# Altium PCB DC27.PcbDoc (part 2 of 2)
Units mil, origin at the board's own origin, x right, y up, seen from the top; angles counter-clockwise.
Board outline 2165.35 x 2165.35 mil, 4 copper layers (Top, Mid-Layer 1, Mid-Layer 2, Bottom), stack 65.59 mil thick; 50 components, 49 nets, 297 pads, 156 vias.
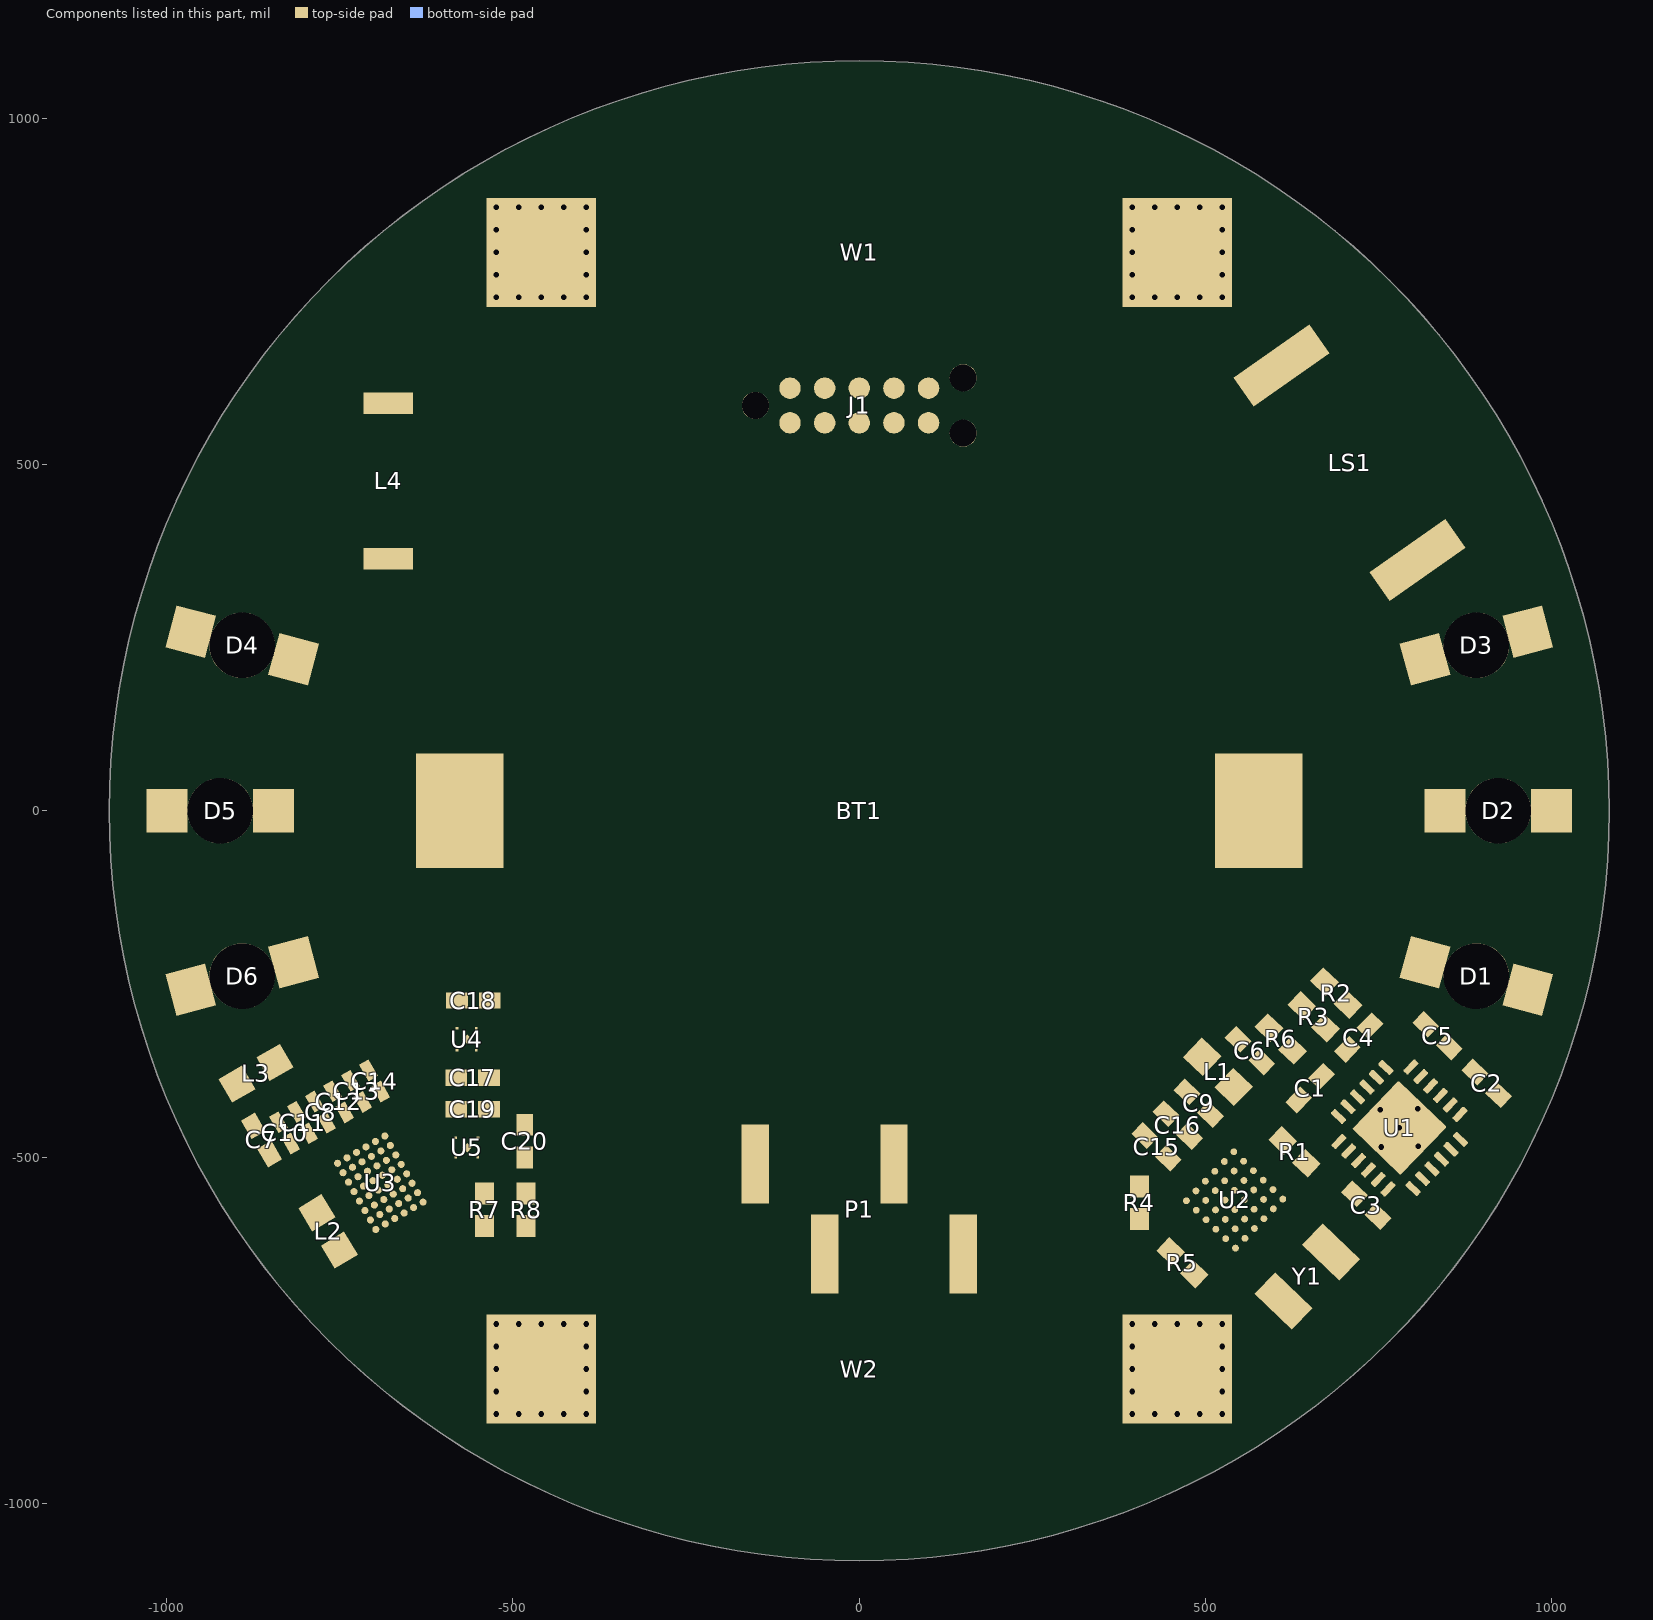
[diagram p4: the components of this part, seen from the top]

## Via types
v1: diameter 16, hole 8, Top to Bottom, 126 vias
v2: diameter 9.45, hole 4.92, Top to Mid-Layer 1, 15 vias
v3: diameter 9.06, hole 4.92, Top to Mid-Layer 1, 13 vias
v4: diameter 9.06, hole 4.92, Top to Bottom, 2 vias

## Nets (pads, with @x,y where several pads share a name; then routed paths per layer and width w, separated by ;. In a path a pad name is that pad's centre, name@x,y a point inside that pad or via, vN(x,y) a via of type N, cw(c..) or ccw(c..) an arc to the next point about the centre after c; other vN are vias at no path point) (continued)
copper on no net: | length 34526.6
  Top w0.89: -300.07,757.6 -249.32,757.6 ; -300.07,758.49 -244.87,758.49 ; -300.07,759.39 -241.3,759.39 ; -300.07,760.28 -236.85,760.28 ; -300.07,761.17 -235.07,761.17 ; -300.07,762.06 -233.29,762.06 ; -300.07,762.95 -231.51,762.95 ; -300.07,763.84 -228.84,763.84 ; -300.07,764.73 -227.06,764.73 ; -300.07,765.62 -226.17,765.62 ; -300.07,766.51 -225.28,766.51 ; -300.07,767.4 -223.5,767.4 ; -300.07,768.29 -222.61,768.29 ; -300.07,769.18 -221.72,769.18 ; -300.07,770.07 -220.83,770.07 ; -300.07,770.96 -219.93,770.96 ; -300.07,771.85 -219.04,771.85 ; -300.07,772.74 -218.15,772.74 ; -300.07,773.63 -217.26,773.63 ; -300.07,774.52 -216.37,774.52 ; -300.07,775.41 -276.03,775.41 ; -300.07,776.3 -276.03,776.3 ; -300.07,777.19 -276.03,777.19 ; -300.07,778.08 -276.03,778.08 ; -300.07,778.97 -276.03,778.97 ; -300.07,779.86 -276.03,779.86 ; -300.07,780.75 -276.03,780.75 ; -300.07,781.64 -276.03,781.64 ; -300.07,782.53 -276.03,782.53 ; -300.07,783.43 -276.03,783.43 ; -300.07,784.32 -276.03,784.32 ; -300.07,785.21 -276.03,785.21 ; -300.07,786.1 -276.03,786.1 ; -300.07,786.99 -276.03,786.99 ; -300.07,787.88 -276.03,787.88 ; -300.07,788.77 -276.03,788.77 ; -300.07,789.66 -276.03,789.66 ; -300.07,790.55 -276.03,790.55 ; -300.07,791.44 -276.03,791.44 ; -300.07,792.33 -276.03,792.33 ; -300.07,793.22 -276.03,793.22 ; -300.07,794.11 -276.03,794.11 ; -300.07,795 -276.03,795 ; -300.07,795.89 -276.03,795.89 ; -300.07,796.78 -276.03,796.78 ; -300.07,797.67 -276.03,797.67 ; -300.07,798.56 -276.03,798.56 ; -300.07,799.45 -276.03,799.45 ; -300.07,800.34 -276.03,800.34 ; -300.07,801.23 -276.03,801.23 ; -300.07,802.12 -276.03,802.12 ; -300.07,803.01 -276.03,803.01 ; -300.07,803.9 -276.03,803.9 ; -300.07,804.79 -276.03,804.79 ; -300.07,805.68 -276.03,805.68 ; -300.07,806.57 -276.03,806.57 ; -300.07,807.47 -276.03,807.47 ; -300.07,808.36 -276.03,808.36 ; -300.07,809.25 -276.03,809.25 ; -300.07,810.14 -276.03,810.14 ; -300.07,811.03 -276.03,811.03 ; -300.07,811.92 -276.03,811.92 ; -300.07,812.81 -276.03,812.81 ; -300.07,813.7 -276.03,813.7 ; -300.07,814.59 -276.03,814.59 ; -300.07,815.48 -276.03,815.48 ; -300.07,816.37 -276.03,816.37 ; -300.07,817.26 -276.03,817.26 ; -300.07,818.15 -276.03,818.15 ; -300.07,819.04 -276.03,819.04 ; -300.07,819.93 -276.03,819.93 ; -300.07,820.82 -276.03,820.82 ; -300.07,821.71 -276.03,821.71 ; -300.07,822.6 -276.03,822.6 ; -300.07,823.49 -276.03,823.49 ; -300.07,824.38 -276.03,824.38 ; -300.07,825.27 -276.03,825.27 ; -300.07,826.16 -276.03,826.16 ; -300.07,827.05 -276.03,827.05 ; -300.07,827.94 -276.03,827.94 ; -300.07,828.83 -276.03,828.83 ; -300.07,829.72 -276.03,829.72 ; -300.07,830.61 -276.03,830.61 ; -300.07,831.51 -276.03,831.51 ; -300.07,832.4 -217.26,832.4 ; -300.07,833.29 -218.15,833.29 ; -300.07,834.18 -219.04,834.18 ; -300.07,835.07 -219.04,835.07 ; -300.07,835.96 -219.93,835.96 ; -300.07,836.85 -220.83,836.85 ; -300.07,837.74 -221.72,837.74 ; -300.07,838.63 -223.5,838.63 ; -300.07,839.52 -224.39,839.52 ; -300.07,840.41 -225.28,840.41 ; -300.07,841.3 -227.06,841.3 ; -300.07,842.19 -227.06,842.19 ; -300.07,843.08 -230.62,843.08 ; -300.07,843.97 -231.51,843.97 ; -300.07,844.86 -233.29,844.86 ; -300.07,845.75 -235.07,845.75 ; -300.07,846.64 -238.63,846.64 ; -300.07,847.53 -241.3,847.53 ; -300.07,848.42 -243.97,848.42 ; -300.07,849.31 -247.54,849.31 ; -299.18,756.71 -260,756.71 ; -299.18,850.2 -257.33,850.2 ; -253.77,775.41 -215.48,775.41 ; -253.77,831.51 -216.37,831.51 ; -251.1,830.61 -215.48,830.61 ; -247.54,776.3 -214.59,776.3 ; -246.65,777.19 -214.59,777.19 ; -246.65,829.72 -214.59,829.72 ; -244.87,778.08 -213.7,778.08 ; -244.87,828.83 -214.59,828.83 ; -243.08,778.97 -213.7,778.97 ; -243.08,779.86 -212.81,779.86 ; -243.08,827.05 -213.7,827.05 ; -243.08,827.94 -214.59,827.94 ; -241.3,826.16 -212.81,826.16 ; -240.41,780.75 -211.92,780.75 ; -239.52,781.64 -211.92,781.64 ; -239.52,782.53 -211.03,782.53 ; -239.52,824.38 -211.92,824.38 ; -239.52,825.27 -211.92,825.27 ; -238.63,783.43 -211.03,783.43 ; -238.63,823.49 -211.03,823.49 ; -237.74,784.32 -210.14,784.32 ; -237.74,822.6 -211.03,822.6 ; -236.85,785.21 -210.14,785.21 ; -236.85,821.71 -210.14,821.71 ; -235.96,786.1 -210.14,786.1 ; -235.96,820.82 -210.14,820.82 ; -235.07,786.99 -210.14,786.99 ; -235.07,787.88 -210.14,787.88 ; -235.07,788.77 -209.25,788.77 ; -235.07,818.15 -210.14,818.15 ; -235.07,819.04 -210.14,819.04 ; -235.07,819.93 -210.14,819.93 ; -234.18,789.66 -209.25,789.66 ; -234.18,790.55 -208.36,790.55 ; -234.18,791.44 -208.36,791.44 ; -234.18,815.48 -209.25,815.48 ; -234.18,816.37 -209.25,816.37 ; -234.18,817.26 -209.25,817.26 ; -233.29,792.33 -208.36,792.33 ; -233.29,793.22 -208.36,793.22 ; -233.29,813.7 -208.36,813.7 ; -233.29,814.59 -208.36,814.59 ; -232.4,794.11 -207.47,794.11 ; -232.4,795 -207.47,795 ; -232.4,795.89 -207.47,795.89 ; -232.4,796.78 -207.47,796.78 ; -232.4,809.25 -207.47,809.25 ; -232.4,810.14 -207.47,810.14 ; -232.4,811.03 -207.47,811.03 ; -232.4,811.92 -207.47,811.92 ; -232.4,812.81 -208.36,812.81 ; -231.51,797.67 -207.47,797.67 ; -231.51,798.56 -207.47,798.56 ; -231.51,799.45 -207.47,799.45 ; -231.51,800.34 -207.47,800.34 ; -231.51,801.23 -207.47,801.23 ; -231.51,802.12 -207.47,802.12 ; -231.51,803.01 -207.47,803.01 ; -231.51,803.9 -207.47,803.9 ; -231.51,804.79 -207.47,804.79 ; -231.51,805.68 -207.47,805.68 ; -231.51,806.57 -207.47,806.57 ; -231.51,807.47 -207.47,807.47 ; -231.51,808.36 -207.47,808.36 ; -189.66,756.71 -121.1,756.71 ; -189.66,757.6 -121.1,757.6 ; -189.66,758.49 -121.1,758.49 ; -189.66,759.39 -121.1,759.39 ; -189.66,760.28 -121.1,760.28 ; -189.66,761.17 -121.1,761.17 ; -189.66,762.06 -121.1,762.06 ; -189.66,762.95 -121.1,762.95 ; -189.66,763.84 -121.1,763.84 ; -189.66,764.73 -121.1,764.73 ; -189.66,765.62 -121.1,765.62 ; -189.66,766.51 -121.1,766.51 ; -189.66,767.4 -121.1,767.4 ; -189.66,768.29 -121.1,768.29 ; -189.66,769.18 -121.1,769.18 ; -189.66,770.07 -121.1,770.07 ; -189.66,770.96 -121.1,770.96 ; -189.66,771.85 -121.1,771.85 ; -189.66,772.74 -121.1,772.74 ; -189.66,773.63 -121.1,773.63 ; -189.66,774.52 -121.1,774.52 ; -189.66,775.41 -165.62,775.41 ; -189.66,776.3 -165.62,776.3 ; -189.66,777.19 -165.62,777.19 ; -189.66,778.08 -165.62,778.08 ; -189.66,778.97 -165.62,778.97 ; -189.66,779.86 -165.62,779.86 ; -189.66,780.75 -165.62,780.75 ; -189.66,781.64 -165.62,781.64 ; -189.66,782.53 -165.62,782.53 ; -189.66,783.43 -165.62,783.43 ; -189.66,784.32 -165.62,784.32 ; -189.66,785.21 -165.62,785.21 ; -189.66,786.1 -165.62,786.1 ; -189.66,786.99 -165.62,786.99 ; -189.66,787.88 -165.62,787.88 ; -189.66,788.77 -165.62,788.77 ; -189.66,789.66 -165.62,789.66 ; -189.66,790.55 -165.62,790.55 ; -189.66,791.44 -165.62,791.44 ; -189.66,792.33 -165.62,792.33 ; -189.66,793.22 -165.62,793.22 ; -189.66,794.11 -165.62,794.11 ; -189.66,795 -165.62,795 ; -189.66,795.89 -165.62,795.89 ; -189.66,796.78 -123.78,796.78 ; -189.66,797.67 -123.78,797.67 ; -189.66,798.56 -123.78,798.56 ; -189.66,799.45 -123.78,799.45 ; -189.66,800.34 -123.78,800.34 ; -189.66,801.23 -123.78,801.23 ; -189.66,802.12 -123.78,802.12 ; -189.66,803.01 -123.78,803.01 ; -189.66,803.9 -123.78,803.9 ; -189.66,804.79 -123.78,804.79 ; -189.66,805.68 -123.78,805.68 ; -189.66,806.57 -123.78,806.57 ; -189.66,807.47 -123.78,807.47 ; -189.66,808.36 -123.78,808.36 ; -189.66,809.25 -123.78,809.25 ; -189.66,810.14 -123.78,810.14 ; -189.66,811.03 -123.78,811.03 ; -189.66,811.92 -123.78,811.92 ; -189.66,812.81 -123.78,812.81 ; -189.66,813.7 -165.62,813.7 ; -189.66,814.59 -165.62,814.59 ; -189.66,815.48 -165.62,815.48 ; -189.66,816.37 -165.62,816.37 ; -189.66,817.26 -165.62,817.26 ; -189.66,818.15 -165.62,818.15 ; -189.66,819.04 -165.62,819.04 ; -189.66,819.93 -165.62,819.93 ; -189.66,820.82 -165.62,820.82 ; -189.66,821.71 -165.62,821.71 ; -189.66,822.6 -165.62,822.6 ; -189.66,823.49 -165.62,823.49 ; -189.66,824.38 -165.62,824.38 ; -189.66,825.27 -165.62,825.27 ; -189.66,826.16 -165.62,826.16 ; -189.66,827.05 -165.62,827.05 ; -189.66,827.94 -165.62,827.94 ; -189.66,828.83 -165.62,828.83 ; -189.66,829.72 -165.62,829.72 ; -189.66,830.61 -165.62,830.61 ; -189.66,831.51 -165.62,831.51 ; -189.66,832.4 -121.99,832.4 ; -189.66,833.29 -121.99,833.29 ; -189.66,834.18 -121.99,834.18 ; -189.66,835.07 -121.99,835.07 ; -189.66,835.96 -121.99,835.96 ; -189.66,836.85 -121.99,836.85 ; -189.66,837.74 -121.99,837.74 ; -189.66,838.63 -121.99,838.63 ; -189.66,839.52 -121.99,839.52 ; -189.66,840.41 -121.99,840.41 ; -189.66,841.3 -121.99,841.3 ; -189.66,842.19 -121.99,842.19 ; -189.66,843.08 -121.99,843.08 ; -189.66,843.97 -121.99,843.97 ; -189.66,844.86 -121.99,844.86 ; -189.66,845.75 -121.99,845.75 ; -189.66,846.64 -121.99,846.64 ; -189.66,847.53 -121.99,847.53 ; -189.66,848.42 -121.99,848.42 ; -189.66,849.31 -121.99,849.31 ; -189.66,850.2 -121.99,850.2 ; -103.3,757.6 -78.37,757.6 ; -103.3,758.49 -78.37,758.49 ; -103.3,759.39 -78.37,759.39 ; -103.3,760.28 -78.37,760.28 ; -103.3,761.17 -78.37,761.17 ; -103.3,762.06 -78.37,762.06 ; -103.3,762.95 -78.37,762.95 ; -103.3,763.84 -78.37,763.84 ; -103.3,764.73 -78.37,764.73 ; -103.3,765.62 -78.37,765.62 ; -103.3,766.51 -78.37,766.51 ; -103.3,767.4 -78.37,767.4 ; -103.3,768.29 -78.37,768.29 ; -103.3,769.18 -78.37,769.18 ; -103.3,770.07 -78.37,770.07 ; -103.3,770.96 -78.37,770.96 ; -103.3,771.85 -78.37,771.85 ; -103.3,772.74 -78.37,772.74 ; -103.3,773.63 -78.37,773.63 ; -103.3,774.52 -78.37,774.52 ; -103.3,775.41 -78.37,775.41 ; -103.3,776.3 -78.37,776.3 ; -103.3,777.19 -78.37,777.19 ; -103.3,778.08 -78.37,778.08 ; -103.3,778.97 -78.37,778.97 ; -103.3,779.86 -78.37,779.86 ; -103.3,780.75 -78.37,780.75 ; -103.3,781.64 -78.37,781.64 ; -103.3,782.53 -78.37,782.53 ; -103.3,783.43 -78.37,783.43 ; -103.3,784.32 -78.37,784.32 ; -103.3,785.21 -78.37,785.21 ; -103.3,786.1 -78.37,786.1 ; -103.3,786.99 -78.37,786.99 ; -103.3,787.88 -78.37,787.88 ; -103.3,788.77 -78.37,788.77 ; -103.3,789.66 -78.37,789.66 ; -103.3,790.55 -78.37,790.55 ; -103.3,791.44 -78.37,791.44 ; -103.3,792.33 -78.37,792.33 ; -103.3,793.22 -78.37,793.22 ; -103.3,794.11 -78.37,794.11 ; -103.3,795 -39.19,795 ; -103.3,795.89 -38.3,795.89 ; -103.3,796.78 -38.3,796.78 ; -103.3,797.67 -38.3,797.67 ; -103.3,798.56 -38.3,798.56 ; -103.3,799.45 -38.3,799.45 ; -103.3,800.34 -38.3,800.34 ; -103.3,801.23 -38.3,801.23 ; -103.3,802.12 -38.3,802.12 ; -103.3,803.01 -38.3,803.01 ; -103.3,803.9 -38.3,803.9 ; -103.3,804.79 -38.3,804.79 ; -103.3,805.68 -38.3,805.68 ; -103.3,806.57 -38.3,806.57 ; -103.3,807.47 -38.3,807.47 ; -103.3,808.36 -38.3,808.36 ; -103.3,809.25 -38.3,809.25 ; -103.3,810.14 -38.3,810.14 ; -103.3,811.03 -38.3,811.03 ; -103.3,811.92 -38.3,811.92 ; -103.3,812.81 -78.37,812.81 ; -103.3,813.7 -78.37,813.7 ; -103.3,814.59 -78.37,814.59 ; -103.3,815.48 -78.37,815.48 ; -103.3,816.37 -78.37,816.37 ; -103.3,817.26 -78.37,817.26 ; -103.3,818.15 -78.37,818.15 ; -103.3,819.04 -78.37,819.04 ; -103.3,819.93 -78.37,819.93 ; -103.3,820.82 -78.37,820.82 ; -103.3,821.71 -78.37,821.71 ; -103.3,822.6 -78.37,822.6 ; -103.3,823.49 -78.37,823.49 ; -103.3,824.38 -78.37,824.38 ; -103.3,825.27 -78.37,825.27 ; -103.3,826.16 -78.37,826.16 ; -103.3,827.05 -78.37,827.05 ; -103.3,827.94 -78.37,827.94 ; -103.3,828.83 -78.37,828.83 ; -103.3,829.72 -78.37,829.72 ; -103.3,830.61 -78.37,830.61 ; -103.3,831.51 -78.37,831.51 ; -103.3,832.4 -39.19,832.4 ; -103.3,833.29 -38.3,833.29 ; -103.3,834.18 -38.3,834.18 ; -103.3,835.07 -38.3,835.07 ; -103.3,835.96 -38.3,835.96 ; -103.3,836.85 -38.3,836.85 ; -103.3,837.74 -38.3,837.74 ; -103.3,838.63 -38.3,838.63 ; -103.3,839.52 -38.3,839.52 ; -103.3,840.41 -38.3,840.41 ; -103.3,841.3 -38.3,841.3 ; -103.3,842.19 -38.3,842.19 ; -103.3,843.08 -38.3,843.08 ; -103.3,843.97 -38.3,843.97 ; -103.3,844.86 -38.3,844.86 ; -103.3,845.75 -38.3,845.75 ; -103.3,846.64 -38.3,846.64 ; -103.3,847.53 -38.3,847.53 ; -103.3,848.42 -38.3,848.42 ; -103.3,849.31 -38.3,849.31 ; -102.41,756.71 -79.26,756.71 ; -102.41,850.2 -39.19,850.2 ; -24.05,797.67 0.88,797.67 ; -24.05,798.56 0.88,798.56 ; -24.05,799.45 0.88,799.45 ; -24.05,800.34 0.88,800.34 ; -24.05,801.23 -0.01,801.23 ; -24.05,802.12 -0.01,802.12 ; -24.05,803.01 -0.01,803.01 ; -24.05,803.9 -0.01,803.9 ; -24.05,804.79 -0.01,804.79 ; -24.05,805.68 -0.01,805.68 ; -24.05,806.57 0.88,806.57 ; -24.05,807.47 0.88,807.47 ; -24.05,808.36 0.88,808.36 ; -23.16,793.22 2.66,793.22 ; -23.16,794.11 2.66,794.11 ; -23.16,795 1.77,795 ; -23.16,795.89 1.77,795.89 ; -23.16,796.78 1.77,796.78 ; -23.16,809.25 0.88,809.25 ; -23.16,810.14 1.77,810.14 ; -23.16,811.03 1.77,811.03 ; -23.16,811.92 1.77,811.92 ; -23.16,812.81 1.77,812.81 ; -22.27,790.55 4.44,790.55 ; -22.27,791.44 3.55,791.44 ; -22.27,792.33 3.55,792.33 ; -22.27,813.7 2.66,813.7 ; -22.27,814.59 3.55,814.59 ; -22.27,815.48 3.55,815.48 ; -21.38,788.77 4.44,788.77 ; -21.38,789.66 4.44,789.66 ; -21.38,816.37 4.44,816.37 ; -21.38,817.26 4.44,817.26 ; -20.49,785.21 8,785.21 ; -20.49,786.1 7.11,786.1 ; -20.49,786.99 6.22,786.99 ; -20.49,787.88 5.33,787.88 ; -20.49,818.15 5.33,818.15 ; -20.49,819.04 5.33,819.04 ; -20.49,819.93 6.22,819.93 ; -20.49,820.82 7.11,820.82 ; -19.6,783.43 9.78,783.43 ; -19.6,784.32 8.89,784.32 ; -19.6,821.71 8.89,821.71 ; -19.6,822.6 8.89,822.6 ; -18.71,781.64 12.45,781.64 ; -18.71,782.53 10.67,782.53 ; -18.71,823.49 9.78,823.49 ; -18.71,824.38 10.67,824.38 ; -17.82,780.75 12.45,780.75 ; -17.82,825.27 12.45,825.27 ; -16.93,778.97 16.9,778.97 ; -16.93,779.86 16.01,779.86 ; -16.93,826.16 14.23,826.16 ; -16.04,776.3 24.03,776.3 ; -16.04,777.19 21.35,777.19 ; -16.04,778.08 18.68,778.08 ; -16.04,827.05 16.01,827.05 ; -16.04,827.94 16.9,827.94 ; -16.04,828.83 18.68,828.83 ; -15.15,829.72 21.35,829.72 ; -14.26,775.41 66.76,775.41 ; -14.26,830.61 28.48,830.61 ; -13.37,773.63 66.76,773.63 ; -13.37,774.52 66.76,774.52 ; -13.37,831.51 65.87,831.51 ; -12.48,772.74 66.76,772.74 ; -12.48,832.4 65.87,832.4 ; -12.48,833.29 65.87,833.29 ; -11.59,771.85 66.76,771.85 ; -11.59,834.18 65.87,834.18 ; -10.7,770.96 66.76,770.96 ; -10.7,835.07 65.87,835.07 ; -9.81,770.07 66.76,770.07 ; -9.81,835.96 65.87,835.96 ; -8.92,769.18 66.76,769.18 ; -8.03,768.29 66.76,768.29 ; -8.03,836.85 65.87,836.85 ; -8.03,837.74 65.87,837.74 ; -6.25,767.4 66.76,767.4 ; -6.25,838.63 65.87,838.63 ; -5.36,766.51 66.76,766.51 ; -5.36,839.52 65.87,839.52 ; -4.47,765.62 66.76,765.62 ; -3.58,764.73 66.76,764.73 ; -3.58,840.41 65.87,840.41 ; -3.58,841.3 65.87,841.3 ; -2.68,763.84 65.87,763.84 ; -1.79,842.19 65.87,842.19 ; -0.01,762.95 62.31,762.95 ; -0.01,843.08 64.98,843.08 ; 1.77,762.06 60.53,762.06 ; 1.77,843.97 63.2,843.97 ; 3.55,761.17 58.75,761.17 ; 3.55,844.86 62.31,844.86 ; 4.44,760.28 57.86,760.28 ; 4.44,845.75 60.53,845.75 ; 8,846.64 57.86,846.64 ; 8.89,759.39 53.41,759.39 ; 9.78,847.53 55.19,847.53 ; 10.67,758.49 50.74,758.49 ; 12.45,848.42 52.52,848.42 ; 13.34,757.6 48.07,757.6 ; 15.12,849.31 49.85,849.31 ; 16.9,756.71 45.39,756.71 ; 18.68,850.2 46.29,850.2 ; 21.35,755.82 40.05,755.82 ; 39.16,830.61 65.87,830.61 ; 43.61,776.3 66.76,776.3 ; 46.29,777.19 66.76,777.19 ; 47.18,829.72 65.87,829.72 ; 48.96,778.08 66.76,778.08 ; 49.85,828.83 65.87,828.83 ; 50.74,778.97 66.76,778.97 ; 51.63,827.94 65.87,827.94 ; 53.41,779.86 66.76,779.86 ; 54.3,827.05 65.87,827.05 ; 56.08,826.16 65.87,826.16 ; 56.97,780.75 66.76,780.75 ; 57.86,781.64 66.76,781.64 ; 58.75,825.27 65.87,825.27 ; 59.64,782.53 66.76,782.53 ; 60.53,824.38 65.87,824.38 ; 61.42,783.43 66.76,783.43 ; 62.31,784.32 66.76,784.32 ; 62.31,823.49 65.87,823.49 ; 63.2,822.6 65.87,822.6 ; 64.98,821.71 65.87,821.71 ; 65.87,785.21 66.76,785.21 ; 81.01,795.89 124.64,795.89 ; 81.01,796.78 124.64,796.78 ; 81.01,797.67 121.08,797.67 ; 81.01,798.56 120.19,798.56 ; 81.01,799.45 119.3,799.45 ; 81.01,800.34 117.51,800.34 ; 81.01,801.23 114.84,801.23 ; 81.01,802.12 113.95,802.12 ; 81.01,803.01 112.17,803.01 ; 81.01,803.9 111.28,803.9 ; 81.01,804.79 109.5,804.79 ; 81.01,805.68 107.72,805.68 ; 81.01,806.57 92.58,806.57 ; 81.01,807.47 90.8,807.47 ; 81.01,808.36 90.8,808.36 ; 81.01,809.25 89.91,809.25 ; 81.01,810.14 89.02,810.14 ; 81.01,811.03 89.02,811.03 ; 81.9,791.44 128.2,791.44 ; 81.9,792.33 131.76,792.33 ; 81.9,793.22 129.09,793.22 ; 81.9,794.11 128.2,794.11 ; 81.9,795 126.42,795 ; 81.9,811.92 89.02,811.92 ; 81.9,812.81 89.02,812.81 ; 81.9,813.7 89.91,813.7 ; 81.9,814.59 89.91,814.59 ; 82.79,786.1 117.51,786.1 ; 82.79,786.99 119.3,786.99 ; 82.79,787.88 120.19,787.88 ; 82.79,788.77 123.75,788.77 ; 82.79,789.66 124.64,789.66 ; 82.79,790.55 126.42,790.55 ; 82.79,815.48 90.8,815.48 ; 82.79,816.37 90.8,816.37 ; 82.79,817.26 90.8,817.26 ; 82.79,818.15 95.26,818.15 ; 82.79,819.04 95.26,819.04 ; 82.79,819.93 95.26,819.93 ; 83.68,784.32 113.06,784.32 ; 83.68,785.21 115.73,785.21 ; 83.68,820.82 94.36,820.82 ; 83.68,821.71 94.36,821.71 ; 84.57,782.53 96.15,782.53 ; 84.57,783.43 97.04,783.43 ; 84.57,822.6 94.36,822.6 ; 84.57,823.49 94.36,823.49 ; 84.57,824.38 95.26,824.38 ; 85.46,780.75 95.26,780.75 ; 85.46,781.64 95.26,781.64 ; 85.46,825.27 95.26,825.27 ; 86.35,778.97 95.26,778.97 ; 86.35,779.86 95.26,779.86 ; 86.35,826.16 95.26,826.16 ; 86.35,827.05 96.15,827.05 ; 87.24,776.3 95.26,776.3 ; 87.24,777.19 95.26,777.19 ; 87.24,778.08 95.26,778.08 ; 87.24,827.94 98.82,827.94 ; 87.24,828.83 113.95,828.83 ; 87.24,829.72 114.84,829.72 ; 88.13,775.41 95.26,775.41 ; 88.13,830.61 115.73,830.61 ; 88.13,831.51 115.73,831.51 ; 89.02,773.63 96.15,773.63 ; 89.02,774.52 95.26,774.52 ; 89.02,832.4 115.73,832.4 ; 89.91,772.74 97.93,772.74 ; 89.91,833.29 115.73,833.29 ; 90.8,770.96 100.6,770.96 ; 90.8,771.85 101.49,771.85 ; 90.8,834.18 117.51,834.18 ; 90.8,835.07 117.51,835.07 ; 90.8,835.96 118.4,835.96 ; 91.69,769.18 99.71,769.18 ; 91.69,770.07 99.71,770.07 ; 91.69,836.85 119.3,836.85 ; 92.58,768.29 99.71,768.29 ; 92.58,837.74 120.19,837.74 ; 93.47,838.63 121.08,838.63 ; 94.36,767.4 99.71,767.4 ; 94.36,839.52 121.97,839.52 ; 95.26,764.73 100.6,764.73 ; 95.26,765.62 99.71,765.62 ; 95.26,766.51 99.71,766.51 ; 95.26,840.41 123.75,840.41 ; 95.26,841.3 124.64,841.3 ; 96.15,763.84 100.6,763.84 ; 96.15,806.57 105.94,806.57 ; 96.15,842.19 125.53,842.19 ; 97.93,762.95 103.27,762.95 ; 97.93,807.47 104.16,807.47 ; 97.93,843.08 128.2,843.08 ; 98.82,808.36 103.27,808.36 ; 98.82,843.97 130.87,843.97 ; 99.71,761.17 173.61,761.17 ; 99.71,762.06 174.5,762.06 ; 99.71,809.25 100.6,809.25 ; 99.71,827.94 113.95,827.94 ; 99.71,844.86 133.54,844.86 ; 99.71,845.75 173.61,845.75 ; 100.6,760.28 173.61,760.28 ; 102.38,759.39 170.94,759.39 ; 102.38,783.43 112.17,783.43 ; 102.38,827.05 113.95,827.05 ; 102.38,846.64 171.83,846.64 ; 103.27,758.49 170.05,758.49 ; 103.27,781.64 108.61,781.64 ; 103.27,782.53 110.39,782.53 ; 103.27,818.15 112.17,818.15 ; 103.27,819.04 112.17,819.04 ; 103.27,825.27 113.06,825.27 ; 103.27,826.16 113.06,826.16 ; 103.27,847.53 170.94,847.53 ; 103.27,848.42 170.05,848.42 ; 104.16,757.6 170.05,757.6 ; 104.16,780.75 107.72,780.75 ; 104.16,817.26 112.17,817.26 ; 104.16,819.93 112.17,819.93 ; 104.16,820.82 112.17,820.82 ; 104.16,821.71 112.17,821.71 ; 104.16,822.6 113.06,822.6 ; 104.16,823.49 113.06,823.49 ; 104.16,824.38 113.06,824.38 ; 105.05,756.71 168.27,756.71 ; 105.05,849.31 169.16,849.31 ; 105.94,816.37 113.06,816.37 ; 105.94,850.2 167.38,850.2 ; 106.83,755.82 167.38,755.82 ; 107.72,762.95 175.39,762.95 ; 107.72,814.59 113.06,814.59 ; 107.72,815.48 113.06,815.48 ; 107.72,851.09 165.59,851.09 ; 108.61,754.93 165.59,754.93 ; 108.61,763.84 166.48,763.84 ; 108.61,771.85 165.59,771.85 ; 108.61,772.74 165.59,772.74 ; 109.5,764.73 166.48,764.73 ; 109.5,765.62 165.59,765.62 ; 109.5,770.07 165.59,770.07 ; 109.5,770.96 165.59,770.96 ; 109.5,813.7 113.06,813.7 ; 109.5,851.98 164.7,851.98 ; 110.39,754.04 163.81,754.04 ; 110.39,766.51 165.59,766.51 ; 110.39,767.4 165.59,767.4 ; 110.39,768.29 165.59,768.29 ; 110.39,769.18 165.59,769.18 ; 110.39,773.63 164.7,773.63 ; 111.28,852.87 162.92,852.87 ; 112.17,753.15 162.03,753.15 ; 112.17,774.52 162.92,774.52 ; 112.17,812.81 113.95,812.81 ; 112.17,853.76 161.14,853.76 ; 113.06,752.26 161.14,752.26 ; 113.06,775.41 161.14,775.41 ; 113.95,854.65 160.25,854.65 ; 114.84,751.37 159.36,751.37 ; 115.73,776.3 159.36,776.3 ; 117.51,777.19 157.58,777.19 ; 117.51,855.55 156.69,855.55 ; 118.4,750.48 155.8,750.48 ; 118.4,818.15 124.64,818.15 ; 119.3,778.08 156.69,778.08 ; 119.3,817.26 123.75,817.26 ; 119.3,819.04 123.75,819.04 ; 120.19,749.59 153.13,749.59 ; 120.19,778.97 154.91,778.97 ; 120.19,812.81 123.75,812.81 ; 120.19,813.7 123.75,813.7 ; 120.19,814.59 122.86,814.59 ; 120.19,815.48 122.86,815.48 ; 120.19,816.37 122.86,816.37 ; 120.19,856.44 154.02,856.44 ; 121.08,811.03 124.64,811.03 ; 121.08,811.92 124.64,811.92 ; 121.97,779.86 153.13,779.86 ; 121.97,809.25 125.53,809.25 ; 121.97,810.14 124.64,810.14 ; 121.97,857.33 152.24,857.33 ; 123.75,748.7 150.46,748.7 ; 123.75,807.47 127.31,807.47 ; 123.75,808.36 126.42,808.36 ; 124.64,780.75 151.35,780.75 ; 124.64,805.68 129.09,805.68 ; 124.64,806.57 128.2,806.57 ; 124.64,826.16 135.32,826.16 ; 124.64,827.05 136.21,827.05 ; 124.64,827.94 136.21,827.94 ; 124.64,828.83 136.21,828.83 ; 124.64,829.72 135.32,829.72 ; 124.64,830.61 134.43,830.61 ; 124.64,858.22 148.68,858.22 ; 125.53,781.64 149.57,781.64 ; 125.53,825.27 134.43,825.27 ; 125.53,831.51 133.54,831.51 ; 126.42,747.81 146.9,747.81 ; 126.42,824.38 133.54,824.38 ; 126.42,832.4 132.65,832.4 ; 127.31,782.53 148.68,782.53 ; 127.31,804.79 132.65,804.79 ; 127.31,823.49 132.65,823.49 ; 128.2,783.43 147.79,783.43 ; 128.2,803.9 134.43,803.9 ; 128.2,833.29 131.76,833.29 ; 129.09,791.44 132.65,791.44 ; 129.09,803.01 147.79,803.01 ; 129.09,822.6 130.87,822.6 ; 129.98,784.32 146.01,784.32 ; 129.98,790.55 134.43,790.55 ; 130.87,802.12 146.01,802.12 ; 131.76,789.66 136.21,789.66 ; 132.65,785.21 143.34,785.21 ; 132.65,788.77 137.1,788.77 ; 132.65,801.23 144.23,801.23 ; 134.43,786.1 142.44,786.1 ; 136.21,786.99 140.66,786.99 ; 136.21,787.88 139.77,787.88 ; 141.55,803.9 148.68,803.9 ; 141.55,827.94 153.13,827.94 ; 141.55,828.83 153.13,828.83 ; 141.55,844.86 173.61,844.86 ; 142.44,826.16 153.13,826.16 ; 142.44,827.05 153.13,827.05 ; 142.44,829.72 153.13,829.72 ; 143.34,825.27 152.24,825.27 ; 143.34,830.61 153.13,830.61 ; 144.23,824.38 151.35,824.38 ; 144.23,831.51 152.24,831.51 ; 145.12,794.11 148.68,794.11 ; 145.12,795 147.79,795 ; 145.12,804.79 149.57,804.79 ; 145.12,823.49 150.46,823.49 ; 145.12,832.4 151.35,832.4 ; 145.12,843.97 175.39,843.97 ; 146.01,793.22 192.31,793.22 ; 146.01,833.29 149.57,833.29 ; 146.9,822.6 148.68,822.6 ; 147.79,805.68 151.35,805.68 ; 147.79,843.08 176.28,843.08 ; 148.68,792.33 191.42,792.33 ; 148.68,806.57 152.24,806.57 ; 148.68,807.47 153.13,807.47 ; 149.57,791.44 191.42,791.44 ; 149.57,808.36 153.13,808.36 ; 150.46,794.11 192.31,794.11 ; 150.46,842.19 178.06,842.19 ; 151.35,790.55 191.42,790.55 ; 151.35,809.25 154.91,809.25 ; 152.24,795 192.31,795 ; 152.24,810.14 154.91,810.14 ; 152.24,811.03 155.8,811.03 ; 152.24,841.3 178.06,841.3 ; 153.13,788.77 190.52,788.77 ; 153.13,789.66 191.42,789.66 ; 153.13,795.89 192.31,795.89 ; 153.13,811.92 155.8,811.92 ; 153.13,812.81 156.69,812.81 ; 153.13,813.7 156.69,813.7 ; 153.13,814.59 156.69,814.59 ; 153.13,815.48 157.58,815.48 ; 153.13,817.26 157.58,817.26 ; 153.13,818.15 158.47,818.15 ; 153.13,819.04 157.58,819.04 ; 153.13,839.52 178.95,839.52 ; 153.13,840.41 178.06,840.41 ; 154.02,816.37 157.58,816.37 ; 154.91,796.78 192.31,796.78 ; 154.91,819.93 155.8,819.93 ; 154.91,838.63 179.84,838.63 ; 156.69,787.88 190.52,787.88 ; 156.69,837.74 181.62,837.74 ; 157.58,786.99 190.52,786.99 ; 157.58,797.67 192.31,797.67 ; 157.58,835.07 182.51,835.07 ; 157.58,835.96 182.51,835.96 ; 157.58,836.85 182.51,836.85 ; 158.47,834.18 183.4,834.18 ; 159.36,786.1 190.52,786.1 ; 159.36,798.56 193.2,798.56 ; 159.36,833.29 184.29,833.29 ; 160.25,785.21 190.52,785.21 ; 160.25,831.51 185.18,831.51 ; 160.25,832.4 185.18,832.4 ; 161.14,799.45 193.2,799.45 ; 161.14,809.25 163.81,809.25 ; 161.14,810.14 165.59,810.14 ; 161.14,811.03 166.48,811.03 ; 161.14,828.83 186.07,828.83 ; 161.14,829.72 186.07,829.72 ; 161.14,830.61 186.07,830.61 ; 162.03,800.34 193.2,800.34 ; 162.03,811.92 168.27,811.92 ; 162.03,812.81 170.05,812.81 ; 162.03,826.16 187.85,826.16 ; 162.03,827.05 186.96,827.05 ; 162.03,827.94 186.96,827.94 ; 162.92,784.32 189.63,784.32 ; 162.92,813.7 172.72,813.7 ; 162.92,814.59 173.61,814.59 ; 162.92,815.48 173.61,815.48 ; 162.92,816.37 173.61,816.37 ; 162.92,817.26 173.61,817.26 ; 162.92,818.15 172.72,818.15 ; 162.92,819.04 172.72,819.04 ; 162.92,819.93 172.72,819.93 ; 162.92,820.82 172.72,820.82 ; 162.92,821.71 173.61,821.71 ; 162.92,822.6 173.61,822.6 ; 162.92,823.49 173.61,823.49 ; 162.92,824.38 174.5,824.38 ; 162.92,825.27 177.17,825.27 ; 164.7,783.43 173.61,783.43 ; 165.59,782.53 171.83,782.53 ; 165.59,801.23 193.2,801.23 ; 166.48,781.64 170.94,781.64 ; 166.48,802.12 193.2,802.12 ; 168.27,780.75 170.94,780.75 ; 168.27,803.01 193.2,803.01 ; 170.05,803.9 181.62,803.9 ; 170.94,804.79 179.84,804.79 ; 171.83,773.63 173.61,773.63 ; 172.72,763.84 177.17,763.84 ; 172.72,772.74 184.29,772.74 ; 173.61,764.73 178.06,764.73 ; 173.61,765.62 178.06,765.62 ; 173.61,766.51 178.95,766.51 ; 173.61,767.4 179.84,767.4 ; 173.61,768.29 180.73,768.29 ; 173.61,769.18 181.62,769.18 ; 173.61,770.07 182.51,770.07 ; 173.61,770.96 182.51,770.96 ; 173.61,771.85 182.51,771.85 ; 173.61,805.68 178.06,805.68 ; 175.39,806.57 178.06,806.57 ; 176.28,773.63 184.29,773.63 ; 176.28,783.43 189.63,783.43 ; 177.17,807.47 178.06,807.47 ; 178.06,774.52 185.18,774.52 ; 178.06,775.41 186.07,775.41 ; 178.06,781.64 188.74,781.64 ; 178.06,782.53 188.74,782.53 ; 178.95,776.3 186.07,776.3 ; 178.95,777.19 186.07,777.19 ; 178.95,779.86 187.85,779.86 ; 178.95,780.75 188.74,780.75 ; 178.95,825.27 188.74,825.27 ; 179.84,778.08 186.96,778.08 ; 179.84,778.97 186.96,778.97 ; 180.73,824.38 188.74,824.38 ; 181.62,814.59 182.51,814.59 ; 181.62,815.48 191.42,815.48 ; 181.62,823.49 189.63,823.49 ; 182.51,816.37 191.42,816.37 ; 182.51,817.26 190.52,817.26 ; 182.51,818.15 190.52,818.15 ; 182.51,819.04 190.52,819.04 ; 182.51,819.93 190.52,819.93 ; 182.51,820.82 190.52,820.82 ; 182.51,821.71 189.63,821.71 ; 182.51,822.6 189.63,822.6 ; 184.29,814.59 191.42,814.59 ; 185.18,803.9 193.2,803.9 ; 186.07,804.79 193.2,804.79 ; 186.07,813.7 191.42,813.7 ; 186.96,805.68 193.2,805.68 ; 186.96,811.92 192.31,811.92 ; 186.96,812.81 192.31,812.81 ; 187.85,806.57 193.2,806.57 ; 187.85,807.47 193.2,807.47 ; 187.85,808.36 193.2,808.36 ; 187.85,809.25 192.31,809.25 ; 187.85,810.14 192.31,810.14 ; 187.85,811.03 192.31,811.03 ; 205.66,756.71 228.81,756.71 ; 205.66,757.6 228.81,757.6 ; 205.66,758.49 228.81,758.49 ; 205.66,759.39 228.81,759.39 ; 205.66,760.28 228.81,760.28 ; 205.66,761.17 228.81,761.17 ; 205.66,762.06 228.81,762.06 ; 205.66,762.95 228.81,762.95 ; 205.66,763.84 228.81,763.84 ; 205.66,764.73 228.81,764.73 ; 205.66,765.62 228.81,765.62 ; 205.66,766.51 228.81,766.51 ; 205.66,767.4 228.81,767.4 ; 205.66,768.29 228.81,768.29 ; 205.66,769.18 228.81,769.18 ; 205.66,770.07 228.81,770.07 ; 205.66,770.96 228.81,770.96 ; 205.66,771.85 228.81,771.85 ; 205.66,772.74 228.81,772.74 ; 205.66,773.63 228.81,773.63 ; 205.66,774.52 228.81,774.52 ; 205.66,775.41 228.81,775.41 ; 205.66,776.3 228.81,776.3 ; 205.66,777.19 228.81,777.19 ; 205.66,778.08 228.81,778.08 ; 205.66,778.97 228.81,778.97 ; 205.66,779.86 228.81,779.86 ; 205.66,780.75 228.81,780.75 ; 205.66,781.64 228.81,781.64 ; 205.66,782.53 228.81,782.53 ; 205.66,783.43 228.81,783.43 ; 205.66,784.32 228.81,784.32 ; 205.66,785.21 228.81,785.21 ; 205.66,786.1 228.81,786.1 ; 205.66,786.99 228.81,786.99 ; 205.66,787.88 228.81,787.88 ; 205.66,788.77 228.81,788.77 ; 205.66,789.66 228.81,789.66 ; 205.66,790.55 228.81,790.55 ; 205.66,791.44 228.81,791.44 ; 205.66,792.33 228.81,792.33 ; 205.66,793.22 228.81,793.22 ; 205.66,794.11 228.81,794.11 ; 205.66,795 228.81,795 ; 205.66,795.89 228.81,795.89 ; 205.66,796.78 228.81,796.78 ; 205.66,797.67 228.81,797.67 ; 205.66,798.56 228.81,798.56 ; 205.66,799.45 228.81,799.45 ; 205.66,800.34 228.81,800.34 ; 205.66,801.23 228.81,801.23 ; 205.66,802.12 228.81,802.12 ; 205.66,803.01 228.81,803.01 ; 205.66,803.9 228.81,803.9 ; 205.66,804.79 228.81,804.79 ; 205.66,805.68 228.81,805.68 ; 205.66,806.57 228.81,806.57 ; 205.66,807.47 228.81,807.47 ; 205.66,808.36 228.81,808.36 ; 205.66,809.25 228.81,809.25 ; 205.66,810.14 228.81,810.14 ; 205.66,811.03 228.81,811.03 ; 205.66,811.92 228.81,811.92 ; 205.66,812.81 228.81,812.81 ; 205.66,813.7 228.81,813.7 ; 205.66,814.59 228.81,814.59 ; 205.66,815.48 256.41,815.48 ; 205.66,816.37 256.41,816.37 ; 205.66,817.26 256.41,817.26 ; 205.66,818.15 254.63,818.15 ; 205.66,819.04 253.74,819.04 ; 205.66,819.93 252.85,819.93 ; 205.66,820.82 251.96,820.82 ; 205.66,821.71 251.96,821.71 ; 205.66,822.6 251.07,822.6 ; 205.66,823.49 250.18,823.49 ; 205.66,824.38 249.29,824.38 ; 205.66,825.27 248.4,825.27 ; 205.66,826.16 247.51,826.16 ; 205.66,827.05 246.62,827.05 ; 205.66,827.94 246.62,827.94 ; 205.66,828.83 245.73,828.83 ; 205.66,829.72 244.84,829.72 ; 205.66,830.61 243.95,830.61 ; 205.66,831.51 243.06,831.51 ; 205.66,832.4 242.17,832.4 ; 205.66,833.29 241.28,833.29 ; 205.66,834.18 240.39,834.18 ; 205.66,835.07 240.39,835.07 ; 205.66,835.96 239.49,835.96 ; 205.66,836.85 238.6,836.85 ; 205.66,837.74 237.71,837.74 ; 205.66,838.63 235.93,838.63 ; 205.66,839.52 235.93,839.52 ; 205.66,840.41 235.93,840.41 ; 205.66,841.3 235.04,841.3 ; 205.66,842.19 234.15,842.19 ; 205.66,843.08 232.37,843.08 ; 205.66,843.97 231.48,843.97 ; 205.66,844.86 231.48,844.86 ; 205.66,845.75 231.48,845.75 ; 205.66,846.64 229.7,846.64 ; 205.66,847.53 228.81,847.53 ; 205.66,848.42 227.92,848.42 ; 205.66,849.31 227.92,849.31 ; 205.66,850.2 227.03,850.2 ; 229.7,814.59 257.3,814.59 ; 230.59,813.7 258.19,813.7 ; 231.48,812.81 259.97,812.81 ; 232.37,811.92 260.86,811.92 ; 233.26,810.14 260.86,810.14 ; 233.26,811.03 260.86,811.03 ; 234.15,809.25 261.75,809.25 ; 235.93,807.47 264.43,807.47 ; 235.93,808.36 263.53,808.36 ; 236.82,806.57 264.43,806.57 ; 237.71,805.68 265.32,805.68 ; 238.6,804.79 266.21,804.79 ; 239.49,803.9 267.1,803.9 ; 240.39,802.12 268.88,802.12 ; 240.39,803.01 267.99,803.01 ; 241.28,801.23 268.88,801.23 ; 243.06,799.45 271.55,799.45 ; 243.06,800.34 270.66,800.34 ; 243.95,797.67 272.44,797.67 ; 243.95,798.56 271.55,798.56 ; 245.73,796.78 273.33,796.78 ; 246.62,795.89 274.22,795.89 ; 247.51,794.11 299.15,794.11 ; 247.51,795 275.11,795 ; 248.4,793.22 299.15,793.22 ; 249.29,792.33 299.15,792.33 ; 250.18,791.44 299.15,791.44 ; 251.07,790.55 299.15,790.55 ; 251.96,788.77 299.15,788.77 ; 251.96,789.66 299.15,789.66 ; 252.85,787.88 299.15,787.88 ; 253.74,786.99 299.15,786.99 ; 254.63,786.1 299.15,786.1 ; 255.52,785.21 299.15,785.21 ; 256.41,783.43 299.15,783.43 ; 256.41,784.32 299.15,784.32 ; 257.3,782.53 299.15,782.53 ; 258.19,781.64 299.15,781.64 ; 259.08,780.75 299.15,780.75 ; 260.86,778.08 299.15,778.08 ; 260.86,778.97 299.15,778.97 ; 260.86,779.86 299.15,779.86 ; 261.75,777.19 299.15,777.19 ; 262.64,776.3 299.15,776.3 ; 264.43,774.52 299.15,774.52 ; 264.43,775.41 299.15,775.41 ; 265.32,772.74 299.15,772.74 ; 265.32,773.63 299.15,773.63 ; 267.1,771.85 299.15,771.85 ; 267.99,770.96 299.15,770.96 ; 268.88,769.18 299.15,769.18 ; 268.88,770.07 299.15,770.07 ; 269.77,768.29 299.15,768.29 ; 270.66,767.4 299.15,767.4 ; 271.55,766.51 299.15,766.51 ; 272.44,765.62 299.15,765.62 ; 273.33,763.84 299.15,763.84 ; 273.33,764.73 299.15,764.73 ; 275.11,762.06 299.15,762.06 ; 275.11,762.95 299.15,762.95 ; 276,761.17 299.15,761.17 ; 276,795 299.15,795 ; 276,795.89 299.15,795.89 ; 276,796.78 299.15,796.78 ; 276,797.67 299.15,797.67 ; 276,798.56 299.15,798.56 ; 276,799.45 299.15,799.45 ; 276,800.34 299.15,800.34 ; 276,801.23 299.15,801.23 ; 276,802.12 299.15,802.12 ; 276,803.01 299.15,803.01 ; 276,803.9 299.15,803.9 ; 276,804.79 299.15,804.79 ; 276,805.68 299.15,805.68 ; 276,806.57 299.15,806.57 ; 276,807.47 299.15,807.47 ; 276,808.36 299.15,808.36 ; 276,809.25 299.15,809.25 ; 276,810.14 299.15,810.14 ; 276,811.03 299.15,811.03 ; 276,811.92 299.15,811.92 ; 276,812.81 299.15,812.81 ; 276,813.7 299.15,813.7 ; 276,814.59 299.15,814.59 ; 276,815.48 299.15,815.48 ; 276,816.37 299.15,816.37 ; 276,817.26 299.15,817.26 ; 276,818.15 299.15,818.15 ; 276,819.04 299.15,819.04 ; 276,819.93 299.15,819.93 ; 276,820.82 299.15,820.82 ; 276,821.71 299.15,821.71 ; 276,822.6 299.15,822.6 ; 276,823.49 299.15,823.49 ; 276,824.38 299.15,824.38 ; 276,825.27 299.15,825.27 ; 276,826.16 299.15,826.16 ; 276,827.05 299.15,827.05 ; 276,827.94 299.15,827.94 ; 276,828.83 299.15,828.83 ; 276,829.72 299.15,829.72 ; 276,830.61 299.15,830.61 ; 276,831.51 299.15,831.51 ; 276,832.4 299.15,832.4 ; 276,833.29 299.15,833.29 ; 276,834.18 299.15,834.18 ; 276,835.07 299.15,835.07 ; 276,835.96 299.15,835.96 ; 276,836.85 299.15,836.85 ; 276,837.74 299.15,837.74 ; 276,838.63 299.15,838.63 ; 276,839.52 299.15,839.52 ; 276,840.41 299.15,840.41 ; 276,841.3 299.15,841.3 ; 276,842.19 299.15,842.19 ; 276,843.08 299.15,843.08 ; 276,843.97 299.15,843.97 ; 276,844.86 299.15,844.86 ; 276,845.75 299.15,845.75 ; 276,846.64 299.15,846.64 ; 276,847.53 299.15,847.53 ; 276,848.42 299.15,848.42 ; 276,849.31 299.15,849.31 ; 276.89,760.28 299.15,760.28 ; 276.89,850.2 299.15,850.2 ; 277.78,759.39 299.15,759.39 ; 278.67,758.49 299.15,758.49 ; 279.56,757.6 299.15,757.6 ; 280.45,756.71 299.15,756.71 ; 306.27,842.19 308.94,842.19 ; 306.27,843.08 308.94,843.08 ; 306.27,843.97 308.94,843.97 ; 306.27,844.86 308.94,844.86 ; 306.27,845.75 308.94,845.75 ; 307.16,840.41 309.83,840.41 ; 307.16,841.3 311.61,841.3 ; 307.16,846.64 309.83,846.64 ; 308.05,839.52 316.07,839.52 ; 308.05,847.53 316.07,847.53 ; 308.94,838.63 315.18,838.63 ; 309.83,842.19 311.61,842.19 ; 309.83,843.08 314.29,843.08 ; 309.83,843.97 314.29,843.97 ; 309.83,844.86 311.61,844.86 ; 309.83,845.75 314.29,845.75 ; 309.83,848.42 315.18,848.42 ; 310.72,849.31 313.4,849.31 ; 312.51,842.19 314.29,842.19 ; 312.51,844.86 314.29,844.86 ; 313.4,841.3 317.85,841.3 ; 314.29,840.41 316.96,840.41 ; 314.29,846.64 316.96,846.64 ; 315.18,842.19 317.85,842.19 ; 315.18,845.75 317.85,845.75 ; 316.07,843.08 318.74,843.08 ; 316.07,843.97 318.74,843.97 ; 316.07,844.86 317.85,844.86
  other v2: -707.91,-555.62 -715.79,-541.98

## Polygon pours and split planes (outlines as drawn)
no net on Drill Drawing (solid): 5181.44,3721.05 5206.44,3537.78 5306.44,3537.78 5331.44,3721.05 5181.44,3721.05
no net on Drill Drawing (solid): 4981.44,3721.05 4981.44,3675.57 5006.44,3675.57 5006.44,1746.44 4981.44,1746.44 4981.44,1700.97 5131.44,1700.97 5131.44,1746.44 5106.44,1746.44 5106.44,3675.57 5131.44,3675.57 5131.44,3721.05 4981.44,3721.05
GND on Mid-Layer 1 "GND-ML1" (solid, pour order 8): -800.22,-412.1 -711.22,-566.25 -656.66,-534.75 -697.16,-464.6 -689.84,-437.28 -728.34,-370.6
no net on Mid-Layer 1 "Mid-Layer 1-No Net" (solid, pour order 6): -1256,-450
GND on Bottom "Bottom-GND" (solid, pour order 4): 0,-1082.68 cw(c0,0) -1082.68,0 cw(c0,0) 0,1082.68 cw(c0,0) 1082.68,0 cw(c0,0)
1V8 on Mid-Layer 2 "Mid-Layer 2-1V8" (solid, pour order 2): 0,-1082.68 cw(c0,0) -1082.68,0 cw(c0,0) 0,1082.68 cw(c0,0) 1082.68,0 cw(c0,0)

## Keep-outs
Top:
  region: -1121,-372.88
Mid-Layer 1:
  rectangle: -1012,419 -752,532
  region: 668.99,-554.37 763.95,-646.07 625.01,-789.94 530.06,-698.24
  region: -575.87,324 -783,324 -783,629 -575.87,629
Mid-Layer 2:
  rectangle: -1012,419 -752,532
  region: 668.99,-554.37 763.95,-646.07 625.01,-789.94 530.06,-698.24
  region: -661.24,-510.49 -626,-475.25 -626,-341.86 -670.65,-297.21 -670.65,274.35 -604,341 -713,341 -713,-318 -667,-364 -667,-451.72 -688.11,-472.83
  region: -575.87,324 -783,324 -783,629 -575.87,629
Bottom:
  rectangle: -1012,419 -752,532
  region: 668.99,-554.37 763.95,-646.07 625.01,-789.94 530.06,-698.24
  region: -575.87,324 -783,324 -783,629 -575.87,629
Keep-Out Layer:
  circle w10: c0,0 r1082.68
  rectangle: -462.73,-720 459.06,720

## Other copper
Top:
  rectangle net GND: 545.97,-113 608.97,19.37
  region net GND: -796.96,-421.76 -779.63,-411.76 -797.63,-380.58 -814.96,-390.58
  region net GND: -866.98,-468.46 -823.68,-443.46 -839.43,-416.18 -882.74,-441.18
  region net GND: -838.41,-465.96 -694.82,-383.06 -708.77,-358.9 -852.35,-441.8
Mid-Layer 1:
  region net NetC12_1: -720.87,-517.55 -694.89,-502.55 -702.89,-488.69 -728.87,-503.69
  region net NetC12_1: -708.74,-510.55 -694.89,-502.55 -742.89,-419.41 -756.74,-427.41

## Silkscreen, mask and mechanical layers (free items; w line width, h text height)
Top Solder:
  drawing of 1149 lines, arcs and shapes, not listed
Board Shape (Round):
  circle w10: c0,0 r1082.68
Board Shape (Square):
  lines w8: -1082.68,-1082.68 1082.68,-1082.68 1082.68,1082.68 -1082.68,1082.68 -1082.68,-1082.68
Drill Drawing:
  drawing of 1809 lines, arcs and shapes, not listed
  text "FABRICATION / ASSEMBLY NOTES:" at -1594,4126 h59.06
  text "(UNLESS OTHERWISE SPECIFIED)" at -1594,4026 h59.06
  text "_________________________" at 4800.2,3955.87 h33.46
  text "DESIGN CROSS SECTION CHART" at 4813.59,3955.87 h33.46
  text "1. MATERIAL: EPOXY GLASS LAMINATE FR-4" at -1594,3826 h59.06
  text "1-4" at 5056.44,3754.51 h33.46 r90
  text "1-2" at 5256.44,3754.51 h33.46 r90
  text "*  SURFACE - AIR 0 MM" at 5604.27,3734.88 h33.46
  text "FINISHED COPPER WEIGHT SHALL BE 1 OZ ON ALL LAYERS" at -1594,3726 h59.06
  text "L1: TOP CONDUCTOR - COPPER 0.033 MM" at 5581.44,3676.43 h33.46
  text "*  DIELECTRIC - FR-4 0.065 MM" at 5604.27,3604.61 h33.46
  text "L2: LAY_2 PLANE - COPPER 0.035 MM" at 5581.44,3541.39 h33.46
  text "2. NUMBER OF ELECTRICAL LAYERS: 4 (SEE STACK-UP DRAWING)" at -1594,3526 h59.06
  text "3. THICKNESS: 1.6mm (FINISHED)" at -1594,3311 h59.06
  text "4. FINISH: IMMERSION PLATE EXPOSED AREAS AFTER APPLYING SOLDER MASK WITH ELECTROLESS NICKEL IMMERSION GOLD, AU < 0.5um" at -1594,3111 h59.06
  text "5. SOLDER MASK: LIQUID PHOTOIMAGEABLE SOLDER MASK PER IPC-SM-840" at -1594,2911 h59.06
  text "COLOR TBD, 10-50um THK, BOTH SIDES, AFTER PLATING. REGISTRATION TO BE WITHIN +/- 50um" at -1594,2811 h59.06
  text "OF THE ASSOCIATED CIRCUIT LAYER." at -1594,2711 h59.06
  text "*  DIELECTRIC - FR-4 1.2 MM" at 5604.27,2700.1 h33.46
  text "6. SILKSCREEN: SILKSCREEN BOTH SIDES USING NONCONDUCTIVE INK COLOR TBD. REMOVE SILKSCREEN FROM EXPOSED COPPER." at -1594,2511 h59.06
  text "7. VIA-IN-PAD: ALL VIA-IN-PAD STRUCTURES TO BE COMPLETELY FILLED WITH NON-CONDUCTIVE EPOXY AND PLATED OVER WITH COPPER." at -1594,2343 h59.06
  text "8. DO NOT PLACE ANY TEST/QA/QC/PCB/MANUFACTURER MARKINGS OR STICKERS ON BOARD" at -1594,2167 h59.06
  text "L3: LAY_3 CONDUCTOR - COPPER 0.035 MM" at 5581.44,1839.62 h33.46
  text "*  DIELECTRIC - FR-4 0.065 MM" at 5604.27,1768.53 h33.46
  text "L4: BOTTOM CONDUCTOR - COPPER 0.033 MM" at 5581.44,1701.82 h33.46
  text "*  SURFACE - AIR 0 MM" at 5604.27,1640.74 h33.46
  text "Symbol" at 3533.13,148 h72
  text "Count" at 4039.01,148 h72
  text "Hole Size" at 4578.87,148 h72
  text "Plated" at 5608.57,148 h72
  text "Hole Type" at 6114.44,148 h72
  text "Drill Layer Pair" at 6848.25,148 h72
  text "Via/Pad" at 8037.9,148 h72
  text "Pad Shape" at 8627.75,148 h72
  text "Template" at 9373.55,148 h72
  text "28" at 4039.01,-2 h60
  text "0.125mm (4.92mil)" at 4578.87,-2 h60
  text "PTH" at 5608.57,-2 h60
  text "Round" at 6114.44,-2 h60
  text "Top - Mid-Layer 1" at 6848.25,-2 h60
  text "Via" at 8037.9,-2 h60
  text "Rounded" at 8627.75,-2 h60
  text "(Mixed)" at 9373.55,-2 h60
  text "28 Total" at 4039.01,-152 h60
  text "GUIDE FOR ADHESIVE PLACEMENT" at 1462,-421 h59.06
  text "Symbol" at 3533.12,-459 h72
  text "Count" at 4039,-459 h72
  text "Hole Size" at 4638.84,-459 h72
  text "Plated" at 5738.52,-459 h72
  text "Hole Type" at 6244.4,-459 h72
  text "Drill Layer Pair" at 6978.2,-459 h72
  text "Via/Pad" at 8167.85,-459 h72
  text "Pad Shape" at 8757.7,-459 h72
  text "Template" at 9503.5,-459 h72
  text "2" at 4039,-609 h60
  text "0.125mm (4.92mil)" at 4638.84,-609 h60
  text "PTH" at 5738.52,-609 h60
  text "Round" at 6244.4,-609 h60
  text "Top - Bottom" at 6978.2,-609 h60
  text "Via" at 8167.85,-609 h60
  text "Rounded" at 8757.7,-609 h60
  text "v23h12m13" at 9503.5,-609 h60
  text "195" at 4039,-759 h60
  text "0.203mm (8.00mil)" at 4638.84,-759 h60
  text "PTH" at 5738.52,-759 h60
  text "Round" at 6244.4,-759 h60
  text "Top - Bottom" at 6978.2,-759 h60
  text "(Mixed)" at 8167.85,-759 h60
  text "Rounded" at 8757.7,-759 h60
  text "(Mixed)" at 9503.5,-759 h60
  text "3" at 4039,-909 h60
  text "0.991mm (39.00mil)" at 4638.84,-909 h60
  text "NPTH" at 5738.52,-909 h60
  text "Round" at 6244.4,-909 h60
  text "Top - Bottom" at 6978.2,-909 h60
  text "Pad" at 8167.85,-909 h60
  text "Rounded" at 8757.7,-909 h60
  text "c99hn99p1099" at 9503.5,-909 h60
  text "6" at 4039,-1059 h60
  text "2.400mm (94.49mil)" at 4638.84,-1059 h60
  text "NPTH" at 5738.52,-1059 h60
  text "Round" at 6244.4,-1059 h60
  text "Top - Bottom" at 6978.2,-1059 h60
  text "Pad" at 8167.85,-1059 h60
  text "Rounded" at 8757.7,-1059 h60
  text "c240hn240" at 9503.5,-1059 h60
  text "206 Total" at 4039,-1209 h60
  text ".PCB_FILE_NAME_NO_PATH" at -1808.14,-2248.88 h70
  text "PCB ARTWORK:" at -1765.83,-2506.09 h29.53
  text "COMPANY:" at -84.73,-2527.75 h39.37
  text "GRAND IDEA STUDIO, INC." at -1765.83,-2604.52 h39.37
  text "Grand Idea Studio, Inc." at 96.86,-2663.88 h49.21
  text "www.GrandIdeaStudio.com" at -1767,-2678 h39.37
  text "TITLE:" at -84.73,-2842.71 h39.37
  text "DEFCON 27 Badge" at 106.86,-2948.88 h49.21
  text "DRAWN:" at -84.73,-3157.67 h39.37
  text "J. Grand" at 110.15,-3277.75 h49.21
  text "DESIGN FILES DISTRIBUTED UNDER A" at -1761.83,-3332.39 h34.45
  text "CREATIVE COMMONS ATTRIBUTION 4.0 INTERNATIONAL LICENSE" at -1761.83,-3411.13 h34.45
  text "ISSUE:" at -84.73,-3472.63 h39.37
  text "DATE:" at 387.71,-3472.63 h39.37
  text "A" at 141,-3486 h49.21
  text "6-17-19" at 682,-3488 h49.21
  text "2019 cc by 4.0" at -1766.09,-3494.28 h34.45

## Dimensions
-1082.68,0 to 1082.68,0 on Drill Drawing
